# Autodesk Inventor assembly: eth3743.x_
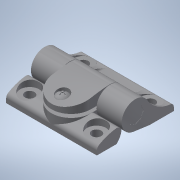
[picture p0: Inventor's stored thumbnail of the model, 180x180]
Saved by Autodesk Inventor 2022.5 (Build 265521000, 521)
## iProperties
Part Number: eth3743.x_
Material: 一般
Document SubType Name: Assembly
Designer: ImaoCorp
Sending System: SOLIDWORKS 2017-2017317
MC: AMD64
MC_MODEL: Intel64 Family 6 Model 60 Stepping 3, GenuineIntel
OS: Windows_NT
FRU: Parasolid Version 29.0, build 201,  4-17-2017
FORMAT: text
GUISE: transmit
KEY: eth3743
FILE: eth3743.x_t
DATE: Mon May 13 14:19:42 2019
Author: ImaoCorp
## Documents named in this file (3)
- X:\14_SW2022-Inv2022\00_全2023-1023新製品(TCC)まで\e\eth3743\ETH3743.iam
- X:\14_SW2022-Inv2022\00_全2023-1023新製品(TCC)まで\e\eth3743\eth3743_01.ipt
- X:\14_SW2022-Inv2022\00_全2023-1023新製品(TCC)まで\e\eth3743\eth3743_02.ipt
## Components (2 placed, 2 different names)
1. eth3743_01
2. eth3743_02
